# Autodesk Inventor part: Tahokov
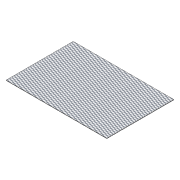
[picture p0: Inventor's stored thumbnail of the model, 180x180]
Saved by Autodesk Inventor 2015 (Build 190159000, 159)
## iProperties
Created: 2016-09
Part Number: Tahokov
Material: Všeobecné
Document SubType Name: Plech
Designer: navara
Density: 1 g/cm^3
Sheet Metal Rule: Výchozí_mm
Appearance: Tahokov
Author: navara
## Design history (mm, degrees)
node "Plocha1"
  sketch "Náčrt1"
    geometry: L1 (-6.972, -905.962)-(1493.028, -905.962); L2 (1493.028, -905.962)-(1493.028, 94.038); L3 (1493.028, 94.038)-(-6.972, 94.038); L4 (-6.972, 94.038)-(-6.972, -905.962)
    constraints: 8 end point, 2 parallel, 1 horizontal, 1 perpendicular
    dimensions: "d0" = 1500 distance of L3.end L2.end; "d1" = 1000 distance of L2.end L1.end
node "Těleso1"
feature "Deska1" dims "Tloušťka" = 5 (derived)
other parameters: "KSoučinitel" = 4.4, "PoloměrOhybu" = 5 (= Tloušťka), "ŠířkaVýštipu" = 5 (= Tloušťka), "HloubkaVýštipu" = 2.5 (= 0.5 x Tloušťka), "MezeraVystřižení" = 0.01, "PřechodovýPoloměr" = 5 (= PoloměrOhybu), "VelikostJacobihoPoloměru" = 5 (= PoloměrOhybu), "VelikostMezery" = 5 (= Tloušťka), "d2" = 5 (= PoloměrOhybu)
